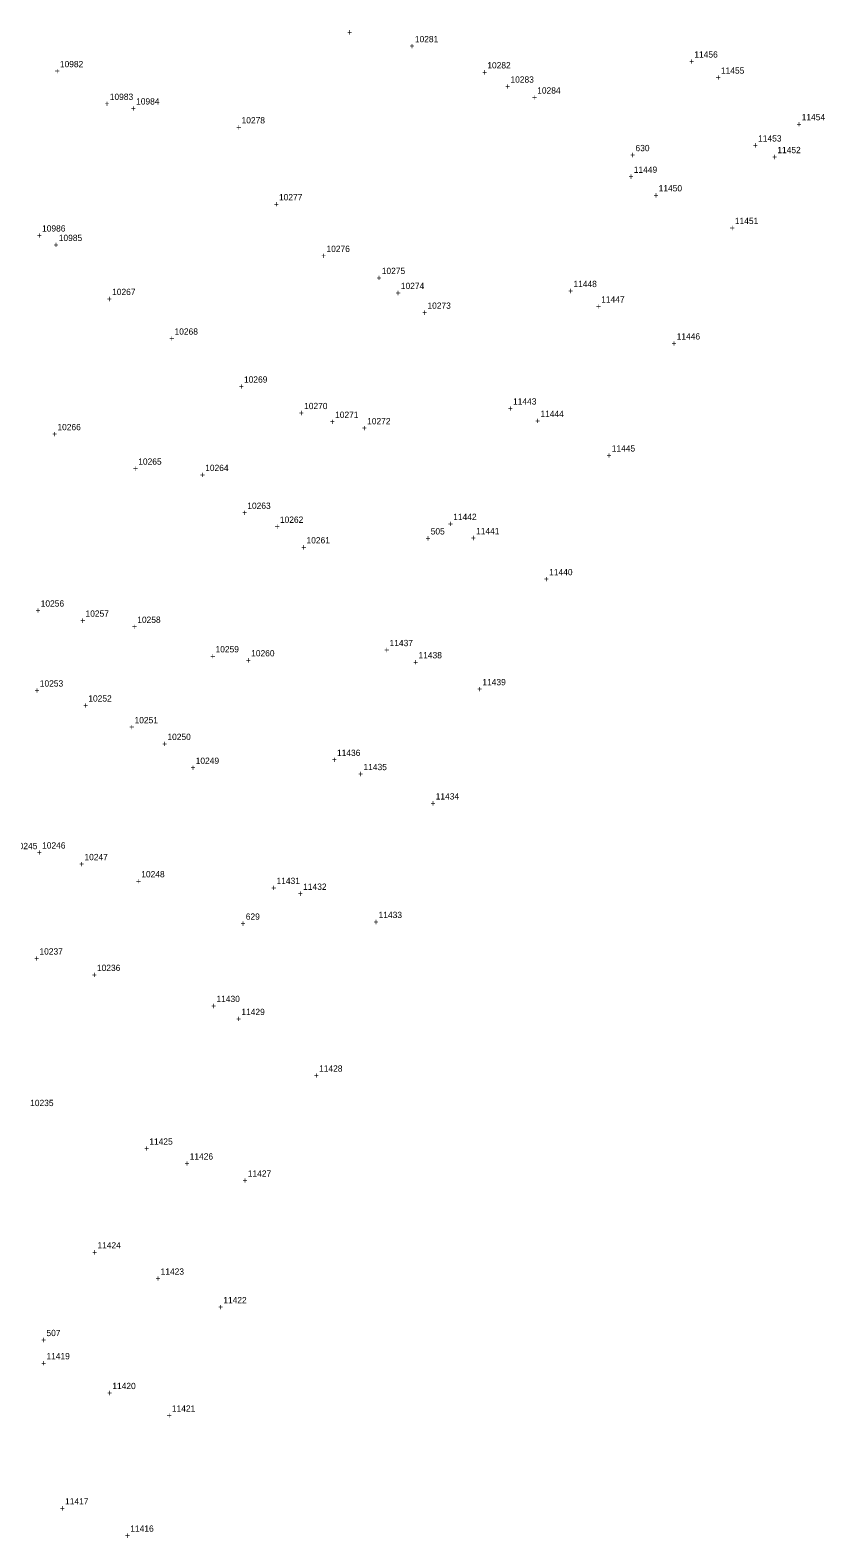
# Model space of a CAD drawing. Extents: x 1160051 to 1162814, y 614604 to 619560.
# Drawn here: x 1160725 to 1161041, y 615863 to 616462 of the extents above; entities that cross this region are included whole.
import ezdxf

# ---------------------------------------------------------------- set-up
doc = ezdxf.new("R2010")
doc.units = 0
for name, color, linetype in [('S_Control_Temp_Traverse', 7, 'Continuous'), ('S_Control_Traverse_Point', 7, 'Continuous'), ('S_Ground_Elevation', 7, 'Continuous'), ('S_Traffic_Sign_DoublePost', 7, 'Continuous'), ('S_Trees_TreeLine', 7, 'Continuous')]:
    doc.layers.add(name, color=color, linetype=linetype)

msp = doc.modelspace()

# ---------------------------------------------------------------- texts
at = {"layer": 'S_Control_Temp_Traverse'}
for s, p in [('+', (1160963.94, 616411.52)), ('+', (1160963.94, 616411.52)), ('630', (1160966, 616414.27)), ('630', (1160966, 616414.27)), ('+', (1160809.05, 616106.08)), ('+', (1160809.05, 616106.08)), ('629', (1160811.11, 616108.83)), ('629', (1160811.11, 616108.83))]:
    msp.add_text(s, height=2.5, dxfattribs=at).set_placement(p)
at = {"layer": 'S_Control_Traverse_Point'}
for s, p in [('505', (1160884.61, 616261.94)), ('505', (1160884.61, 616261.94)), ('505', (1160884.61, 616261.94)), ('505', (1160884.61, 616261.94)), ('505', (1160884.61, 616261.94)), ('505', (1160884.61, 616261.94)), ('505', (1160884.61, 616261.94)), ('505', (1160884.61, 616261.94)), ('+', (1160882.55, 616259.19)), ('+', (1160882.55, 616259.19)), ('+', (1160882.55, 616259.19)), ('+', (1160882.55, 616259.19)), ('+', (1160882.55, 616259.19)), ('+', (1160882.55, 616259.19)), ('+', (1160882.55, 616259.19)), ('+', (1160882.55, 616259.19)), ('507', (1160731.9, 615943.36)), ('507', (1160731.9, 615943.36)), ('507', (1160731.9, 615943.36)), ('507', (1160731.9, 615943.36)), ('507', (1160731.9, 615943.36)), ('+', (1160729.84, 615940.61)), ('+', (1160729.84, 615940.61)), ('+', (1160729.84, 615940.61)), ('+', (1160729.84, 615940.61)), ('+', (1160729.84, 615940.61))]:
    msp.add_text(s, height=2.5, dxfattribs=at).set_placement(p)
at = {"layer": 'S_Ground_Elevation'}
for s, p in [('+', (1160851.41, 616460.27)), ('10281', (1160878.31, 616457.57)), ('+', (1160876.24, 616454.82)), ('11456', (1160989.38, 616451.46)), ('10982', (1160737.23, 616447.64)), ('10282', (1160907.1, 616447.15)), ('+', (1160987.32, 616448.71)), ('11455', (1160999.95, 616445.06)), ('+', (1160735.17, 616444.89)), ('+', (1160905.04, 616444.4)), ('10283', (1160916.31, 616441.49)), ('+', (1160997.89, 616442.31)), ('10983', (1160757.06, 616434.63)), ('+', (1160914.25, 616438.74)), ('+', (1160924.87, 616434.4)), ('10284', (1160926.93, 616437.15)), ('+', (1160755, 616431.88)), ('+', (1160765.46, 616430.06)), ('10984', (1160767.52, 616432.81)), ('+', (1160807.38, 616422.55)), ('10278', (1160809.44, 616425.3)), ('+', (1161029.99, 616423.78)), ('11454', (1161032.05, 616426.53)), ('11449', (1160965.32, 616405.66)), ('+', (1160963.26, 616402.91)), ('11450', (1160975.21, 616398.28)), ('+', (1160822.26, 616391.99)), ('10277', (1160824.32, 616394.74)), ('+', (1160973.15, 616395.53)), ('11451', (1161005.49, 616385.31)), ('+', (1160728.08, 616379.58)), ('10986', (1160730.14, 616382.33)), ('+', (1161003.43, 616382.56)), ('+', (1160734.73, 616375.81)), ('10985', (1160736.79, 616378.56)), ('10276', (1160843.19, 616374.22)), ('+', (1160841.13, 616371.47)), ('+', (1160863.1, 616362.69)), ('10275', (1160865.16, 616365.44)), ('10267', (1160757.99, 616357.09)), ('+', (1160870.68, 616356.72)), ('10274', (1160872.74, 616359.47)), ('+', (1160939.28, 616357.5)), ('11448', (1160941.35, 616360.25)), ('+', (1160755.93, 616354.34)), ('10273', (1160883.3, 616351.63)), ('+', (1160950.31, 616351.35)), ('11447', (1160952.37, 616354.1)), ('+', (1160881.24, 616348.88)), ('+', (1160780.74, 616338.6)), ('10268', (1160782.8, 616341.35)), ('11446', (1160982.37, 616339.42)), ('+', (1160980.31, 616336.67)), ('+', (1160808.34, 616319.53)), ('10269', (1160810.4, 616322.28)), ('11443', (1160917.32, 616313.57)), ('+', (1160832.23, 616309)), ('10270', (1160834.29, 616311.75)), ('10271', (1160846.61, 616308.27)), ('+', (1160915.26, 616310.82)), ('11444', (1160928.21, 616308.63)), ('10266', (1160736.24, 616303.38)), ('+', (1160844.55, 616305.52)), ('+', (1160857.28, 616302.99)), ('10272', (1160859.34, 616305.74)), ('+', (1160926.15, 616305.88)), ('+', (1160734.18, 616300.63)), ('10265', (1160768.37, 616289.66)), ('+', (1160954.51, 616292.15)), ('11445', (1160956.57, 616294.9)), ('+', (1160766.31, 616286.91)), ('+', (1160792.92, 616284.41)), ('10264', (1160794.98, 616287.16)), ('10263', (1160811.71, 616272.12)), ('+', (1160809.65, 616269.37)), ('10262', (1160824.67, 616266.57)), ('11442', (1160893.55, 616267.7)), ('+', (1160822.61, 616263.82)), ('+', (1160891.48, 616264.95)), ('11441', (1160902.64, 616262.06)), ('+', (1160833.19, 616255.64)), ('10261', (1160835.25, 616258.39)), ('+', (1160900.57, 616259.31)), ('+', (1160929.63, 616243)), ('11440', (1160931.69, 616245.75)), ('+', (1160727.55, 616230.53)), ('10256', (1160729.61, 616233.28)), ('10257', (1160747.42, 616229.25)), ('+', (1160745.36, 616226.5)), ('+', (1160765.92, 616224.07)), ('10258', (1160767.98, 616226.82)), ('11437', (1160868.25, 616217.56)), ('+', (1160797.03, 616212.34)), ('10259', (1160799.09, 616215.09)), ('10260', (1160813.25, 616213.49)), ('+', (1160866.19, 616214.81)), ('11438', (1160879.76, 616212.72)), ('+', (1160811.19, 616210.74)), ('+', (1160877.7, 616209.97)), ('10253', (1160729.25, 616201.49)), ('11439', (1160905.14, 616202.02)), ('+', (1160727.19, 616198.74)), ('10252', (1160748.53, 616195.54)), ('+', (1160903.08, 616199.27)), ('+', (1160746.47, 616192.79)), ('+', (1160764.85, 616184.17)), ('10251', (1160766.91, 616186.92)), ('+', (1160777.9, 616177.51)), ('10250', (1160779.96, 616180.26)), ('10249', (1160791.21, 616170.78)), ('+', (1160845.29, 616171.18)), ('11436', (1160847.36, 616173.93)), ('+', (1160789.15, 616168.03)), ('+', (1160855.83, 616165.53)), ('11435', (1160857.89, 616168.28)), ('+', (1160884.52, 616153.87)), ('11434', (1160886.59, 616156.62)), ('+', (1160728.1, 616134.37)), ('10246', (1160730.17, 616137.12)), ('+', (1160744.93, 616129.75)), ('10247', (1160746.99, 616132.5)), ('+', (1160767.51, 616122.94)), ('10248', (1160769.57, 616125.69)), ('11431', (1160823.33, 616123.05)), ('+', (1160821.27, 616120.3)), ('+', (1160831.86, 616117.97)), ('11432', (1160833.92, 616120.72)), ('11433', (1160863.9, 616109.5)), ('+', (1160861.84, 616106.75)), ('+', (1160727.05, 616092.24)), ('10237', (1160729.11, 616094.99)), ('10236', (1160751.97, 616088.47)), ('+', (1160749.91, 616085.72)), ('11430', (1160799.46, 616076.12)), ('+', (1160797.4, 616073.37)), ('+', (1160807.3, 616068.21)), ('11429', (1160809.36, 616070.96)), ('+', (1160838.17, 616045.7)), ('11428', (1160840.24, 616048.45)), ('10235', (1160725.42, 616034.77)), ('11425', (1160772.77, 616019.45)), ('+', (1160770.71, 616016.7)), ('11426', (1160788.82, 616013.52)), ('+', (1160786.76, 616010.77)), ('+', (1160809.87, 616003.97)), ('11427', (1160811.93, 616006.72)), ('11424', (1160752.15, 615978.2)), ('+', (1160750.09, 615975.45)), ('11423', (1160777.27, 615967.77)), ('+', (1160775.21, 615965.02)), ('11422', (1160802.18, 615956.43)), ('+', (1160800.12, 615953.68)), ('+', (1160729.81, 615931.39)), ('11419', (1160731.87, 615934.14)), ('+', (1160756.01, 615919.55)), ('11420', (1160758.07, 615922.3)), ('11421', (1160781.74, 615913.33)), ('+', (1160779.68, 615910.58)), ('11417', (1160739.28, 615876.45)), ('+', (1160737.22, 615873.7)), ('11416', (1160765.21, 615865.62)), ('+', (1160763.14, 615862.87))]:
    msp.add_text(s, height=2.5, dxfattribs=at).set_placement(p)
at = {"layer": 'S_Traffic_Sign_DoublePost'}
for s, p in [('+', (1161012.68, 616415.36)), ('11453', (1161014.74, 616418.11)), ('+', (1161020.3, 616410.73)), ('11452', (1161022.36, 616413.48))]:
    msp.add_text(s, height=2.5, dxfattribs=at).set_placement(p)
at = {"layer": 'S_Trees_TreeLine'}
msp.add_text('10245', height=2.5, dxfattribs=at).set_placement((1160718.99, 616136.88))

doc.saveas('drawing.dxf')
